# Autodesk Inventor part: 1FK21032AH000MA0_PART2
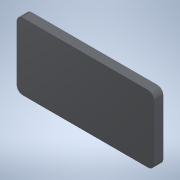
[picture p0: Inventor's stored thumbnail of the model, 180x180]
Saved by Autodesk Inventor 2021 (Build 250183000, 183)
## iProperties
Created: 2025-04
Part Number: 1FK21032AH000MA0_PART2
Material: Generic
Catalog Web Link: www.3dfindit.com
Description: -Servo synchronous motor
Document SubType Name: Modeling
Designer: psAdmin
Mass: 2.9597 g
Surface Area: 23.6483 cm^2
Volume: 2.9597 cm^3
Density: 1 g/cm^3
Appearance: PSOLRGB-38-46-56
Category: PARTsolutions
Title: 1FK21032AH000MA0_PART2
Author: Cadenas PARTsolutions
Comments: Servo synchronous motor
Sending System: PARTsolutions
Preprocessor: ST-DEVELOPER v19.3
PSOL_IDENT_0: {$CADENAS_DATA/23d-libs/siemens_ag/_cat_/45/10/1fk21032ah000ma0.prj},213 {VTYP=3D},{NB=1FK21032AH000
PSOL_IDENT_1: MA0_PART2},{LINA=1FK21032AH000MA0_PART2},{NN=1FK21032AH000MA0_PART2},{NOPRJ=TRUE},{DATE=19.08.2025 1
PSOL_IDENT_2: 4:00:35},{GEOMDATE=30.07.2025 02:02:03},{VERSION=},{LINEID=10},{WBVAR=},{WBNUMERIC=}  {NB=1FK21032AH
PSOL_IDENT_3: 000MA0_PART2},{LINA=1FK21032AH000MA0_PART2},{KT=DUMMY},{PREVIEW=../../../_pool_/14/8e/p_d211_xx_0042
PSOL_IDENT_4: 6j.png},{DESCSHORT=SIMOTICS S-1FK2 HD, SINAMICS S210 3AC 400V-480V, 0.59 Nm, 4500 rpm},{DESCLONG=SIM
PSOL_IDENT_5: OTICS S-1FK2 HD servo motor M0=0.64 Nm; PN = 0.28 kW at nN=4500 rpm (380-480 V); PN = 0.167 kW at nN=
PSOL_IDENT_6: 2500 rpm (200-240 V); degree of protection IP64; cylindrical shaft D14 x 30 mm; absolute encoder 22-
PSOL_IDENT_7: bit + 12-bit multiturn (encoder AM22DQC); with OCC interface; plug size M17, rotatable; SIMOTICS S-1
PSOL_IDENT_8: FK2 servomotorfor a wide range of uses in industrial environments. SIMOTICS S‑1FK2 servomotors are c
PSOL_IDENT_9: ompact synchronous motors with a high dynamic performance that set themselves apart as a result of t
PSOL_IDENT_10: heir high power density, degree of protection and overload capability. The motors are available in t
PSOL_IDENT_11: wo variants: as High Dynamic variant (highest dynamic performance as a result of the low intrinsic m
PSOL_IDENT_12: oment of inertia for applications demanding a high dynamic performance with low moved masses) - and
PSOL_IDENT_13: as Compact variant (precise and stable closed-loop control for medium up to large moved masses as a
PSOL_IDENT_14: result of a medium intrinsic moment of inertia). SIMOTICSS‑1FK2 servomotors fully exploit their stre
PSOL_IDENT_15: ngths in a system with the SINAMICSS210 frequency converter and simple connection using the one cabl
PSOL_IDENT_16: e connection (OCC). Advantages include the short control and positioning times, fast and precise cor
PSOL_IDENT_17: rection of disturbing quantities as well as stable control with a high dynamic performance. The serv
PSOL_IDENT_18: o motors can be configured to address a wide range of requirements. For example with and without hol
PSOL_IDENT_19: ding brake, IP64 or IP65 degree of protection, singleturn or multiturn absolute encoders - to name j
PSOL_IDENT_20: ust a few. Further, the servomotors are available in different shaft heights extending from 20 to 10
PSOL_IDENT_21: 0. A shaft sealing ring is available to achieve an IP65 degree of protection and for subsequent moun
PSOL_IDENT_22: ting at the motor or as spare part. SIMOTICS - the optimum motor for each and every motion control a
PSOL_IDENT_23: pplication.},{INTNO=195125335004},{SUPPLIERALTNO=1FK2103-2AH00-0MA0},{MANUID=1FK21032AH000MA0},{MANU
PSOL_IDENT_24: NAME=Siemens},{MANUTYPEDESC=SYNCHRONOUS MOTOR 1FK2 HD 0,64 NM},{AAU732=SIMOTICS},{AAO057=S-1FK2},{AA
PSOL_IDENT_25: U734=SIMOTICS S-1FK2 HD servo motor M0=0.64 Nm; PN = 0.28 kW at nN=4500 rpm (380-480 V); PN = 0.167
PSOL_IDENT_26: kW at nN=2500 rpm (200-240 V); degree of protection IP64; cylindrical shaft D14 x 30 mm; absolute en
PSOL_IDENT_27: coder 22-bit + 12-bit multiturn (encoder AM22DQC); with OCC interface; plug size M17, rotatable;},{A
PSOL_IDENT_28: AW338=SYNCHRONOUS MOTOR 1FK2 HD 0,64 NM},{AAO742=SIMOTICS},{AAO663=4034106444624},{NOCUPEROU=1},{PRI
PSOL_IDENT_29: CEQUANTITY=1},{QUANTITYMIN=1},{QUANTITYINT=1},{CTN=85015100},{COO=RO},{AAO676=1FK2103-2AH00-0MA0},{A
PSOL_IDENT_30: AO677=Siemens AG},{ORDERUNIT=C62},{CONTENTUNIT=C62}
NB: 1FK21032AH000MA0_PART2
NT: Servo synchronous motor
NBSYN: $MANUID._PART2
LINA: 1FK21032AH000MA0_PART2
CATALOG: SIEMENS
PREVIEW: ../../../_pool_/14/8e/p_d211_xx_00426j.png
DESCSHORT: SIMOTICS S-1FK2 HD, SINAMICS S210 3AC 400V-480V, 0.59 Nm, 4500 rpm
DESCLONG: SIMOTICS S-1FK2 HD servo motor M0=0.64 Nm; PN = 0.28 kW at nN=4500 rpm (380-480 V); PN = 0.167 kW at nN=2500 rpm (200-240 V); degree of protection IP64; cylindr
INTNO: 195125335004
SUPPLIERALTNO: 1FK2103-2AH00-0MA0
MANUID: 1FK21032AH000MA0
MANUNAME: Siemens
MANUTYPEDESC: SYNCHRONOUS MOTOR 1FK2 HD 0,64 NM
AAU732: SIMOTICS
AAO057: S-1FK2
AAU734: SIMOTICS S-1FK2 HD servo motor M0=0.64 Nm; PN = 0.28 kW at nN=4500 rpm (380-480 V); PN = 0.167 kW at nN=2500 rpm (200-240 V); degree of protection IP64; cylindr
AAW338: SYNCHRONOUS MOTOR 1FK2 HD 0,64 NM
AAO742: SIMOTICS
AAO663: 4034106444624.0
NOCUPEROU: 1
PRICEQUANTITY: 1
QUANTITYMIN: 1
QUANTITYINT: 1
CTN: 85015100
COO: RO
ARTICLENO: 1FK21032AH000MA0_PART2
BOMINFO: 1FK21032AH000MA0_PART2
CREATOR: CADENAS GmbH
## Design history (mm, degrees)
feature "2025_04_17_15_00_20_0635"
body "Solid1"
